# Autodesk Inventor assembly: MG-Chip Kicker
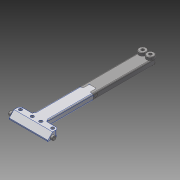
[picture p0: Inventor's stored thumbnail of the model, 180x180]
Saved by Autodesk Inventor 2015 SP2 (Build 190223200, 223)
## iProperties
Created: 2015-08
Part Number: MG-Chip Kicker
Document SubType Name: Assembly
Designer: rYan
Author: rYan
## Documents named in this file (6)
- E:\TIGERs GIT\Hardware\mechanik\2016\Inventor\Kicker\Chip\MG-Chip Kicker.iam
- E:\TIGERs GIT\Hardware\mechanik\2016\Inventor\Kicker\Kicker Eisen.ipt
- E:\TIGERs GIT\Hardware\mechanik\2016\Inventor\Inhaltscenter\de-DE\ISO 2338(1)\ISO 2338 - 3 m6 x 12DIN EN.ipt
- E:\TIGERs GIT\Hardware\mechanik\2016\Inventor\Kicker\Kicker Mitte.ipt
- E:\TIGERs GIT\Hardware\mechanik\2016\Inventor\Inhaltscenter\de-DE\DIN 7984\DIN 7984 - M4 x 6.ipt
- E:\TIGERs GIT\Hardware\mechanik\2016\Inventor\Inhaltscenter\de-DE\ISO 4762(1)\ISO 4762 - M2 x 5DIN EN ISO.ipt
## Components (7 placed, 5 different names)
1. Kicker Eisen:1 — Passend:1, Fluchtend:1, Fluchtend:2, Passend:2, Fluchtend:3, Einfügen:1, Einfügen:2
2. Kicker Mitte:1 — Passend:1, Fluchtend:1, Fluchtend:2, Einfügen:3, Einfügen:4
3. DIN EN ISO 2338 3 m6 x 12:1 — Passend:2, Fluchtend:3
4. DIN 7984 M4 x 6:1 — Einfügen:2
5. DIN 7984 M4 x 6:2 — Einfügen:1
6. DIN EN ISO 4762 M2 x 5:1 — Einfügen:3
7. DIN EN ISO 4762 M2 x 5:2 — Einfügen:4
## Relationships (9: Insert 4, Flush 3, Mate 2)
- Passend:1 [Mate]: Kicker Eisen:1 ↔ Kicker Mitte:1
- Fluchtend:1 [Flush]: Kicker Eisen:1 ↔ Kicker Mitte:1
- Fluchtend:2 [Flush]: Kicker Eisen:1 ↔ Kicker Mitte:1
- Passend:2 [Mate]: Kicker Eisen:1 ↔ DIN EN ISO 2338 3 m6 x 12:1
- Fluchtend:3 [Flush]: Kicker Eisen:1 ↔ DIN EN ISO 2338 3 m6 x 12:1
- Einfügen:1 [Insert]: Kicker Eisen:1 ↔ DIN 7984 M4 x 6:2
- Einfügen:2 [Insert]: Kicker Eisen:1 ↔ DIN 7984 M4 x 6:1
- Einfügen:3 [Insert]: Kicker Mitte:1 ↔ DIN EN ISO 4762 M2 x 5:1
- Einfügen:4 [Insert]: Kicker Mitte:1 ↔ DIN EN ISO 4762 M2 x 5:2
